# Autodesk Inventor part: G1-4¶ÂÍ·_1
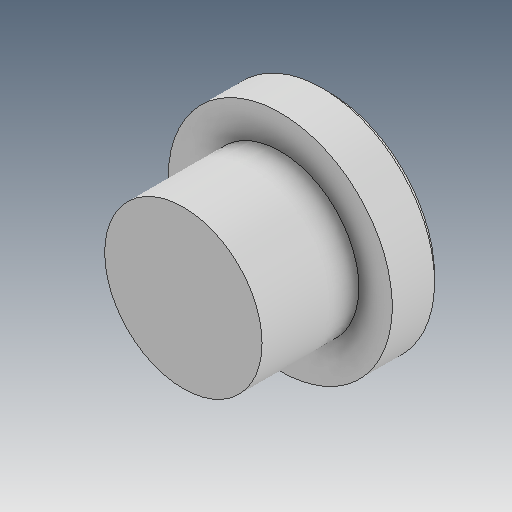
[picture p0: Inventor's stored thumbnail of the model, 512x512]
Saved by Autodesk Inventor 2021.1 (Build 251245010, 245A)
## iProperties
Created: 2019-12
Part Number: G1-4¶ÂÍ·_1
Material: Ogólny
Document SubType Name: Modeling
Designer: user
Density: 1 g/cm^3
Appearance: Domyślna
Author: user
Revision Number: ÈÎºÎ
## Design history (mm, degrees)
feature "ÊäÈë1"
node "Bryła1"
